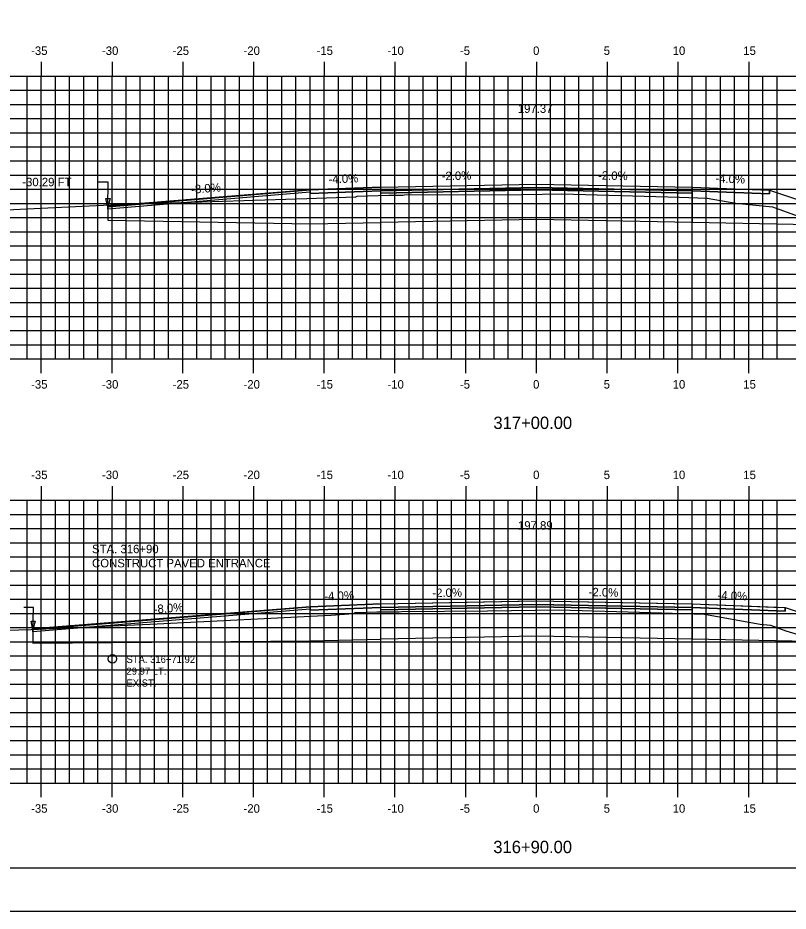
# Model space of a CAD drawing. Extents: x 1138985 to 1139155, y 608981 to 609091.
# Drawn here: x 1139031.3 to 1139085.7, y 608981.3 to 609044.5 of the extents above; entities that cross this region are included whole.
import ezdxf

# ---------------------------------------------------------------- set-up
doc = ezdxf.new("R2010")
doc.units = 0
for name, color, linetype in [('ANNOTATION', 7, 'Continuous'), ('BORDER', 7, 'Continuous'), ('D_Roadway_Centerline', 7, 'Continuous'), ('D_Roadway_Centerline_Text', 7, 'Continuous'), ('D_Roadway_Edge_Shoulder', 7, 'Continuous'), ('D_Roadway_Edge_TW', 7, 'Continuous'), ('D_Roadway_Pavement', 7, 'Continuous'), ('D_Roadway_SubGrade', 7, 'Continuous'), ('D_Text_Monospaced', 7, 'Continuous'), ('D_Text_Standard', 7, 'Continuous'), ('H_V ANNOTATION', 7, 'Continuous'), ('MAJOR', 7, 'Continuous'), ('MINOR', 7, 'Continuous'), ('PLOT BOUNDARY', 7, 'Continuous'), ('S_Drainage_Invert', 7, 'Continuous'), ('S_Roadway_Centerline', 7, 'Continuous')]:
    doc.layers.add(name, color=color, linetype=linetype)

msp = doc.modelspace()

# ---------------------------------------------------------------- linework, layer by layer
for points in [[(1139037.654, 609031.141), (1139051.949, 609032.284), (1139056.949, 609032.484), (1139067.949, 609032.704), (1139078.949, 609032.484), (1139084.428, 609032.265), (1139092.057, 609029.722), (1139095.057, 609028.722), (1139095.244, 609028.66)], [(1139032.35, 609001.237), (1139049.597, 609002.617), (1139051.949, 609002.805), (1139056.349, 609002.981), (1139056.949, 609003.005), (1139066.629, 609003.198), (1139067.949, 609003.225), (1139077.629, 609003.031), (1139078.949, 609003.005), (1139084.726, 609002.774), (1139085.52, 609002.742), (1139092.173, 609000.524), (1139093.079, 609000.222), (1139095.719, 608999.342), (1139096.079, 608999.222), (1139096.573, 608999.058), (1139096.638, 608999.036)]]:
    msp.add_lwpolyline(points)
at = {"layer": 'BORDER'}
msp.add_lwpolyline([(1138992.949, 608984.335), (1139152.949, 608984.335), (1139152.949, 609089.335), (1138992.949, 609089.335)], close=True, dxfattribs=at)
at = {"layer": 'D_Roadway_Edge_Shoulder'}
for points in [[(1139051.949, 609032.284), (1139051.949, 609032.118), (1139037.654, 609030.934), (1139037.654, 609031.101)], [(1139056.949, 609032.484), (1139051.949, 609032.284), (1139051.949, 609032.034), (1139056.949, 609032.234)], [(1139078.949, 609032.484), (1139084.428, 609032.265), (1139084.428, 609032.015), (1139078.949, 609032.234)], [(1139051.949, 609002.805), (1139051.949, 609002.638), (1139032.35, 609001.03), (1139032.35, 609001.197)], [(1139056.949, 609003.005), (1139051.949, 609002.805), (1139051.949, 609002.555), (1139056.949, 609002.755)], [(1139078.949, 609003.005), (1139085.52, 609002.742), (1139085.52, 609002.492), (1139078.949, 609002.755)]]:
    msp.add_lwpolyline(points, close=True, dxfattribs=at)
at = {"layer": 'D_Roadway_Edge_TW'}
for points in [[(1139056.949, 609032.234), (1139056.949, 609032.484), (1139067.949, 609032.704), (1139078.949, 609032.484), (1139078.949, 609032.234), (1139067.949, 609032.454)], [(1139056.949, 609002.755), (1139056.949, 609003.005), (1139067.949, 609003.225), (1139078.949, 609003.005), (1139078.949, 609002.755), (1139067.949, 609002.975)]]:
    msp.add_lwpolyline(points, close=True, dxfattribs=at)
at = {"layer": 'D_Roadway_Pavement'}
for points in [[(1139056.949, 609032.068), (1139056.949, 609032.234), (1139067.949, 609032.454), (1139078.949, 609032.234), (1139078.949, 609032.068), (1139067.949, 609032.288)], [(1139056.949, 609002.588), (1139056.949, 609002.755), (1139067.949, 609002.975), (1139078.949, 609002.755), (1139078.949, 609002.588), (1139067.949, 609002.808)]]:
    msp.add_lwpolyline(points, close=True, dxfattribs=at)
at = {"layer": 'D_Roadway_SubGrade'}
for points in [[(1139037.654, 609030.141), (1139051.949, 609029.884), (1139056.949, 609029.984), (1139056.949, 609032.068), (1139056.949, 609032.234), (1139051.949, 609032.034), (1139051.949, 609032.284), (1139037.654, 609031.141)], [(1139056.949, 609029.984), (1139056.949, 609032.068), (1139067.949, 609032.288), (1139078.949, 609032.068), (1139078.949, 609029.984), (1139067.949, 609030.204)], [(1139078.949, 609032.068), (1139078.949, 609032.234), (1139084.428, 609032.015), (1139084.428, 609032.265), (1139084.428, 609032.265), (1139092.057, 609029.722), (1139078.949, 609029.984)], [(1139032.35, 609000.237), (1139051.949, 609000.405), (1139056.949, 609000.505), (1139056.949, 609002.588), (1139056.949, 609002.755), (1139051.949, 609002.555), (1139051.949, 609002.805), (1139032.35, 609001.237)], [(1139056.949, 609000.505), (1139056.949, 609002.588), (1139067.949, 609002.808), (1139078.949, 609002.588), (1139078.949, 609000.505), (1139067.949, 609000.725)], [(1139078.949, 609002.588), (1139078.949, 609002.755), (1139085.52, 609002.492), (1139085.52, 609002.742), (1139085.52, 609002.742), (1139093.079, 609000.222), (1139078.949, 609000.505)]]:
    msp.add_lwpolyline(points, close=True, dxfattribs=at)
at = {"layer": 'D_Text_Standard'}
for points in [[(1139037.654, 609031.101), (1139037.679, 609032.848), (1139036.999, 609032.848)], [(1139032.35, 609001.197), (1139032.4, 609002.742), (1139031.72, 609002.742)]]:
    msp.add_lwpolyline(points, dxfattribs=at)
for points in [[(1139037.654, 609031.101), (1139037.517, 609031.685), (1139037.808, 609031.681)], [(1139032.35, 609001.197), (1139032.223, 609001.783), (1139032.514, 609001.774)]]:
    msp.add_lwpolyline(points, close=True, dxfattribs=at)
at = {"layer": 'MAJOR'}
for p, q in [((1139032.949, 609041.337), (1139032.949, 609040.335)), ((1139037.949, 609041.337), (1139037.949, 609040.335)), ((1139042.949, 609041.337), (1139042.949, 609040.335)), ((1139047.949, 609041.337), (1139047.949, 609040.335)), ((1139052.949, 609041.337), (1139052.949, 609040.335)), ((1139057.949, 609041.337), (1139057.949, 609040.335)), ((1139062.949, 609041.337), (1139062.949, 609040.335)), ((1139067.949, 609041.337), (1139067.949, 609040.335)), ((1139072.949, 609041.337), (1139072.949, 609040.335)), ((1139077.949, 609041.337), (1139077.949, 609040.335)), ((1139082.949, 609041.337), (1139082.949, 609040.335)), ((1138997.949, 609040.335), (1139137.949, 609040.335)), ((1138997.949, 609040.335), (1139137.949, 609040.335)), ((1139032.949, 609020.335), (1139032.949, 609040.335)), ((1139037.949, 609020.335), (1139037.949, 609040.335)), ((1139042.949, 609020.335), (1139042.949, 609040.335)), ((1139047.949, 609020.335), (1139047.949, 609040.335)), ((1139052.949, 609020.335), (1139052.949, 609040.335)), ((1139057.949, 609020.335), (1139057.949, 609040.335)), ((1139062.949, 609020.335), (1139062.949, 609040.335)), ((1139067.949, 609020.335), (1139067.949, 609040.335)), ((1139072.949, 609020.335), (1139072.949, 609040.335)), ((1139077.949, 609020.335), (1139077.949, 609040.335)), ((1139082.949, 609020.335), (1139082.949, 609040.335)), ((1138997.949, 609035.335), (1139137.949, 609035.335)), ((1138997.949, 609030.335), (1139137.949, 609030.335)), ((1138997.949, 609025.335), (1139137.949, 609025.335)), ((1138997.949, 609020.335), (1139137.949, 609020.335)), ((1138997.949, 609020.335), (1139137.949, 609020.335)), ((1139032.949, 609019.333), (1139032.949, 609020.335)), ((1139037.949, 609019.333), (1139037.949, 609020.335)), ((1139042.949, 609019.333), (1139042.949, 609020.335)), ((1139047.949, 609019.333), (1139047.949, 609020.335)), ((1139052.949, 609019.333), (1139052.949, 609020.335)), ((1139057.949, 609019.333), (1139057.949, 609020.335)), ((1139062.949, 609019.333), (1139062.949, 609020.335)), ((1139067.949, 609019.333), (1139067.949, 609020.335)), ((1139072.949, 609019.333), (1139072.949, 609020.335)), ((1139077.949, 609019.333), (1139077.949, 609020.335)), ((1139082.949, 609019.333), (1139082.949, 609020.335)), ((1139032.949, 609011.337), (1139032.949, 609010.335)), ((1139037.949, 609011.337), (1139037.949, 609010.335)), ((1139042.949, 609011.337), (1139042.949, 609010.335)), ((1139047.949, 609011.337), (1139047.949, 609010.335)), ((1139052.949, 609011.337), (1139052.949, 609010.335)), ((1139057.949, 609011.337), (1139057.949, 609010.335)), ((1139062.949, 609011.337), (1139062.949, 609010.335)), ((1139067.949, 609011.337), (1139067.949, 609010.335)), ((1139072.949, 609011.337), (1139072.949, 609010.335)), ((1139077.949, 609011.337), (1139077.949, 609010.335)), ((1139082.949, 609011.337), (1139082.949, 609010.335)), ((1138997.949, 609010.335), (1139137.949, 609010.335)), ((1138997.949, 609010.335), (1139137.949, 609010.335)), ((1139032.949, 608990.335), (1139032.949, 609010.335)), ((1139037.949, 608990.335), (1139037.949, 609010.335)), ((1139042.949, 608990.335), (1139042.949, 609010.335)), ((1139047.949, 608990.335), (1139047.949, 609010.335)), ((1139052.949, 608990.335), (1139052.949, 609010.335)), ((1139057.949, 608990.335), (1139057.949, 609010.335)), ((1139062.949, 608990.335), (1139062.949, 609010.335)), ((1139067.949, 608990.335), (1139067.949, 609010.335)), ((1139072.949, 608990.335), (1139072.949, 609010.335)), ((1139077.949, 608990.335), (1139077.949, 609010.335)), ((1139082.949, 608990.335), (1139082.949, 609010.335)), ((1138997.949, 609005.335), (1139137.949, 609005.335)), ((1138997.949, 609000.335), (1139137.949, 609000.335)), ((1138997.949, 608995.335), (1139137.949, 608995.335)), ((1138997.949, 608990.335), (1139137.949, 608990.335)), ((1138997.949, 608990.335), (1139137.949, 608990.335)), ((1139032.949, 608989.333), (1139032.949, 608990.335)), ((1139037.949, 608989.333), (1139037.949, 608990.335)), ((1139042.949, 608989.333), (1139042.949, 608990.335)), ((1139047.949, 608989.333), (1139047.949, 608990.335)), ((1139052.949, 608989.333), (1139052.949, 608990.335)), ((1139057.949, 608989.333), (1139057.949, 608990.335)), ((1139062.949, 608989.333), (1139062.949, 608990.335)), ((1139067.949, 608989.333), (1139067.949, 608990.335)), ((1139072.949, 608989.333), (1139072.949, 608990.335)), ((1139077.949, 608989.333), (1139077.949, 608990.335)), ((1139082.949, 608989.333), (1139082.949, 608990.335))]:
    msp.add_line(p, q, dxfattribs=at)
at = {"layer": 'MINOR'}
for p, q in [((1139031.949, 609020.335), (1139031.949, 609040.335)), ((1139033.949, 609020.335), (1139033.949, 609040.335)), ((1139034.949, 609020.335), (1139034.949, 609040.335)), ((1139035.949, 609020.335), (1139035.949, 609040.335)), ((1139036.949, 609020.335), (1139036.949, 609040.335)), ((1139038.949, 609020.335), (1139038.949, 609040.335)), ((1139039.949, 609020.335), (1139039.949, 609040.335)), ((1139040.949, 609020.335), (1139040.949, 609040.335)), ((1139041.949, 609020.335), (1139041.949, 609040.335)), ((1139043.949, 609020.335), (1139043.949, 609040.335)), ((1139044.949, 609020.335), (1139044.949, 609040.335)), ((1139045.949, 609020.335), (1139045.949, 609040.335)), ((1139046.949, 609020.335), (1139046.949, 609040.335)), ((1139048.949, 609020.335), (1139048.949, 609040.335)), ((1139049.949, 609020.335), (1139049.949, 609040.335)), ((1139050.949, 609020.335), (1139050.949, 609040.335)), ((1139051.949, 609020.335), (1139051.949, 609040.335)), ((1139053.949, 609020.335), (1139053.949, 609040.335)), ((1139054.949, 609020.335), (1139054.949, 609040.335)), ((1139055.949, 609020.335), (1139055.949, 609040.335)), ((1139056.949, 609020.335), (1139056.949, 609040.335)), ((1139058.949, 609020.335), (1139058.949, 609040.335)), ((1139059.949, 609020.335), (1139059.949, 609040.335)), ((1139060.949, 609020.335), (1139060.949, 609040.335)), ((1139061.949, 609020.335), (1139061.949, 609040.335)), ((1139063.949, 609020.335), (1139063.949, 609040.335)), ((1139064.949, 609020.335), (1139064.949, 609040.335)), ((1139065.949, 609020.335), (1139065.949, 609040.335)), ((1139066.949, 609020.335), (1139066.949, 609040.335)), ((1139068.949, 609020.335), (1139068.949, 609040.335)), ((1139069.949, 609020.335), (1139069.949, 609040.335)), ((1139070.949, 609020.335), (1139070.949, 609040.335)), ((1139071.949, 609020.335), (1139071.949, 609040.335)), ((1139073.949, 609020.335), (1139073.949, 609040.335)), ((1139074.949, 609020.335), (1139074.949, 609040.335)), ((1139075.949, 609020.335), (1139075.949, 609040.335)), ((1139076.949, 609020.335), (1139076.949, 609040.335)), ((1139078.949, 609020.335), (1139078.949, 609040.335)), ((1139079.949, 609020.335), (1139079.949, 609040.335)), ((1139080.949, 609020.335), (1139080.949, 609040.335)), ((1139081.949, 609020.335), (1139081.949, 609040.335)), ((1139083.949, 609020.335), (1139083.949, 609040.335)), ((1139084.949, 609020.335), (1139084.949, 609040.335)), ((1138997.949, 609039.335), (1139137.949, 609039.335)), ((1138997.949, 609038.335), (1139137.949, 609038.335)), ((1138997.949, 609037.335), (1139137.949, 609037.335)), ((1138997.949, 609036.335), (1139137.949, 609036.335)), ((1138997.949, 609034.335), (1139137.949, 609034.335)), ((1138997.949, 609033.335), (1139137.949, 609033.335)), ((1138997.949, 609032.335), (1139137.949, 609032.335)), ((1138997.949, 609031.335), (1139137.949, 609031.335)), ((1138997.949, 609029.335), (1139137.949, 609029.335)), ((1138997.949, 609028.335), (1139137.949, 609028.335)), ((1138997.949, 609027.335), (1139137.949, 609027.335)), ((1138997.949, 609026.335), (1139137.949, 609026.335)), ((1138997.949, 609024.335), (1139137.949, 609024.335)), ((1138997.949, 609023.335), (1139137.949, 609023.335)), ((1138997.949, 609022.335), (1139137.949, 609022.335)), ((1138997.949, 609021.335), (1139137.949, 609021.335)), ((1139031.949, 608990.335), (1139031.949, 609010.335)), ((1139033.949, 608990.335), (1139033.949, 609010.335)), ((1139034.949, 608990.335), (1139034.949, 609010.335)), ((1139035.949, 608990.335), (1139035.949, 609010.335)), ((1139036.949, 608990.335), (1139036.949, 609010.335)), ((1139038.949, 608990.335), (1139038.949, 609010.335)), ((1139039.949, 608990.335), (1139039.949, 609010.335)), ((1139040.949, 608990.335), (1139040.949, 609010.335)), ((1139041.949, 608990.335), (1139041.949, 609010.335)), ((1139043.949, 608990.335), (1139043.949, 609010.335)), ((1139044.949, 608990.335), (1139044.949, 609010.335)), ((1139045.949, 608990.335), (1139045.949, 609010.335)), ((1139046.949, 608990.335), (1139046.949, 609010.335)), ((1139048.949, 608990.335), (1139048.949, 609010.335)), ((1139049.949, 608990.335), (1139049.949, 609010.335)), ((1139050.949, 608990.335), (1139050.949, 609010.335)), ((1139051.949, 608990.335), (1139051.949, 609010.335)), ((1139053.949, 608990.335), (1139053.949, 609010.335)), ((1139054.949, 608990.335), (1139054.949, 609010.335)), ((1139055.949, 608990.335), (1139055.949, 609010.335)), ((1139056.949, 608990.335), (1139056.949, 609010.335)), ((1139058.949, 608990.335), (1139058.949, 609010.335)), ((1139059.949, 608990.335), (1139059.949, 609010.335)), ((1139060.949, 608990.335), (1139060.949, 609010.335)), ((1139061.949, 608990.335), (1139061.949, 609010.335)), ((1139063.949, 608990.335), (1139063.949, 609010.335)), ((1139064.949, 608990.335), (1139064.949, 609010.335)), ((1139065.949, 608990.335), (1139065.949, 609010.335)), ((1139066.949, 608990.335), (1139066.949, 609010.335)), ((1139068.949, 608990.335), (1139068.949, 609010.335)), ((1139069.949, 608990.335), (1139069.949, 609010.335)), ((1139070.949, 608990.335), (1139070.949, 609010.335)), ((1139071.949, 608990.335), (1139071.949, 609010.335)), ((1139073.949, 608990.335), (1139073.949, 609010.335)), ((1139074.949, 608990.335), (1139074.949, 609010.335)), ((1139075.949, 608990.335), (1139075.949, 609010.335)), ((1139076.949, 608990.335), (1139076.949, 609010.335)), ((1139078.949, 608990.335), (1139078.949, 609010.335)), ((1139079.949, 608990.335), (1139079.949, 609010.335)), ((1139080.949, 608990.335), (1139080.949, 609010.335)), ((1139081.949, 608990.335), (1139081.949, 609010.335)), ((1139083.949, 608990.335), (1139083.949, 609010.335)), ((1139084.949, 608990.335), (1139084.949, 609010.335)), ((1138997.949, 609009.335), (1139137.949, 609009.335)), ((1138997.949, 609008.335), (1139137.949, 609008.335)), ((1138997.949, 609007.335), (1139137.949, 609007.335)), ((1138997.949, 609006.335), (1139137.949, 609006.335)), ((1138997.949, 609004.335), (1139137.949, 609004.335)), ((1138997.949, 609003.335), (1139137.949, 609003.335)), ((1138997.949, 609002.335), (1139137.949, 609002.335)), ((1138997.949, 609001.335), (1139137.949, 609001.335)), ((1138997.949, 608999.335), (1139137.949, 608999.335)), ((1138997.949, 608998.335), (1139137.949, 608998.335)), ((1138997.949, 608997.335), (1139137.949, 608997.335)), ((1138997.949, 608996.335), (1139137.949, 608996.335)), ((1138997.949, 608994.335), (1139137.949, 608994.335)), ((1138997.949, 608993.335), (1139137.949, 608993.335)), ((1138997.949, 608992.335), (1139137.949, 608992.335)), ((1138997.949, 608991.335), (1139137.949, 608991.335))]:
    msp.add_line(p, q, dxfattribs=at)
at = {"layer": 'PLOT BOUNDARY'}
msp.add_lwpolyline([(1138984.856, 608981.276), (1139154.856, 608981.276), (1139154.856, 609091.276), (1138984.856, 609091.276)], close=True, dxfattribs=at)
at = {"layer": 'S_Drainage_Invert'}
msp.add_circle((1139037.975, 608999.125), 0.3, dxfattribs=at)
at = {"layer": 'S_Roadway_Centerline'}
for points in [[(1139008.964, 609030.568), (1139013.802, 609030.617), (1139018.789, 609030.701), (1139029.012, 609030.802), (1139036.333, 609031.172), (1139038.36, 609031.267), (1139051.717, 609031.692), (1139055.192, 609031.796), (1139055.286, 609031.839), (1139057.512, 609031.91), (1139058.507, 609031.916), (1139058.609, 609031.937), (1139066.993, 609031.972), (1139069.75, 609032.014), (1139078.062, 609031.769), (1139080.017, 609031.708), (1139082.039, 609031.345), (1139084.628, 609031.083), (1139088.442, 609029.697)], [(1138997.949, 609000.594), (1138998.212, 609000.594), (1139010.067, 609000.697), (1139023.809, 609001.027), (1139029.59, 609001.116), (1139032.226, 609001.203), (1139041.14, 609001.588), (1139053.415, 609002.2), (1139055.024, 609002.334), (1139055.142, 609002.388), (1139056.663, 609002.437), (1139058.25, 609002.447), (1139058.412, 609002.48), (1139064.476, 609002.505), (1139069.549, 609002.583), (1139076.026, 609002.392), (1139079.831, 609002.273), (1139083.768, 609001.567), (1139084.499, 609001.493), (1139085.575, 609001.102), (1139092.172, 608999.144)]]:
    msp.add_lwpolyline(points, dxfattribs=at)

# ---------------------------------------------------------------- texts
at = {"layer": 'ANNOTATION'}
for s, rotation, p in [('-2.0%', 1.14576, (1139061.252, 609032.971)), ('-2.0%', 358.85424, (1139072.292, 609033.018)), ('-4.0%', 2.29061, (1139053.265, 609032.738)), ('-4.0%', 357.70939, (1139080.584, 609032.82)), ('-8.0%', 4.57392, (1139043.569, 609032.017)), ('-4.0%', 2.29061, (1139052.965, 609003.246)), ('-2.0%', 1.14576, (1139060.592, 609003.478)), ('-2.0%', 358.85424, (1139071.632, 609003.551)), ('-4.0%', 357.70939, (1139080.733, 609003.334)), ('-8.0%', 4.57392, (1139040.918, 609002.325))]:
    msp.add_text(s, height=0.6, rotation=rotation, dxfattribs=at).set_placement(p)
for s, p in [('STA. 316+90', (1139036.537, 609006.592)), ('CONSTRUCT PAVED ENTRANCE', (1139036.537, 609005.59))]:
    msp.add_text(s, height=0.6, dxfattribs=at).set_placement(p)
at = {"layer": 'D_Roadway_Centerline'}
for s, p in [('C', (1139067.943, 609032.704)), ('L', (1139067.949, 609032.697)), ('C', (1139067.943, 609003.225)), ('L', (1139067.949, 609003.217))]:
    msp.add_text(s, height=0.0146, dxfattribs=at).set_placement(p)
at = {"layer": 'D_Roadway_Centerline_Text'}
for s, p in [('197.37', (1139066.627, 609037.736)), ('197.89', (1139066.638, 609008.257))]:
    msp.add_text(s, height=0.6, dxfattribs=at).set_placement(p)
at = {"layer": 'D_Text_Monospaced'}
for s, height, p in [('STA. 316+71.92', 0.49998, (1139038.969, 608998.835)), ('29.97 LT.', 0.5, (1139038.969, 608998.001)), ('EXIST. ', 0.5, (1139038.969, 608997.161))]:
    msp.add_text(s, height=height, dxfattribs=at).set_placement(p)
at = {"layer": 'D_Text_Standard'}
msp.add_text('-30.29 FT', height=0.6, dxfattribs=at).set_placement((1139031.605, 609032.548))
at = {"layer": 'H_V ANNOTATION'}
for s, height, p in [('-35', 0.6, (1139032.229, 609041.835)), ('-30', 0.6, (1139037.237, 609041.835)), ('-25', 0.6, (1139042.234, 609041.835)), ('-20', 0.6, (1139047.242, 609041.835)), ('-15', 0.6, (1139052.406, 609041.835)), ('-10', 0.6, (1139057.414, 609041.835)), ('-5', 0.6, (1139062.539, 609041.835)), ('0', 0.6, (1139067.708, 609041.835)), ('5', 0.6, (1139072.7, 609041.835)), ('10', 0.6, (1139077.574, 609041.835)), ('15', 0.6, (1139082.566, 609041.835)), ('-35', 0.6, (1139032.229, 609018.235)), ('-30', 0.6, (1139037.237, 609018.235)), ('-25', 0.6, (1139042.234, 609018.235)), ('-20', 0.6, (1139047.242, 609018.235)), ('-15', 0.6, (1139052.406, 609018.235)), ('-10', 0.6, (1139057.414, 609018.235)), ('-5', 0.6, (1139062.539, 609018.235)), ('0', 0.6, (1139067.708, 609018.235)), ('5', 0.6, (1139072.7, 609018.235)), ('10', 0.6, (1139077.574, 609018.235)), ('15', 0.6, (1139082.566, 609018.235)), ('317+00.00', 0.875, (1139064.905, 609015.378)), ('-35', 0.6, (1139032.229, 609011.835)), ('-30', 0.6, (1139037.237, 609011.835)), ('-25', 0.6, (1139042.234, 609011.835)), ('-20', 0.6, (1139047.242, 609011.835)), ('-15', 0.6, (1139052.406, 609011.835)), ('-10', 0.6, (1139057.414, 609011.835)), ('-5', 0.6, (1139062.539, 609011.835)), ('0', 0.6, (1139067.708, 609011.835)), ('5', 0.6, (1139072.7, 609011.835)), ('10', 0.6, (1139077.574, 609011.835)), ('15', 0.6, (1139082.566, 609011.835)), ('-35', 0.6, (1139032.229, 608988.235)), ('-30', 0.6, (1139037.237, 608988.235)), ('-25', 0.6, (1139042.234, 608988.235)), ('-20', 0.6, (1139047.242, 608988.235)), ('-15', 0.6, (1139052.406, 608988.235)), ('-10', 0.6, (1139057.414, 608988.235)), ('-5', 0.6, (1139062.539, 608988.235)), ('0', 0.6, (1139067.708, 608988.235)), ('5', 0.6, (1139072.7, 608988.235)), ('10', 0.6, (1139077.574, 608988.235)), ('15', 0.6, (1139082.566, 608988.235)), ('316+90.00', 0.875, (1139064.898, 608985.378))]:
    msp.add_text(s, height=height, dxfattribs=at).set_placement(p)
at = {"layer": 'S_Roadway_Centerline'}
for s, p in [('C', (1139069.745, 609032.014)), ('L', (1139069.75, 609032.007)), ('C', (1139069.544, 609002.583)), ('L', (1139069.549, 609002.576))]:
    msp.add_text(s, height=0.0146, dxfattribs=at).set_placement(p)

doc.saveas('drawing.dxf')
